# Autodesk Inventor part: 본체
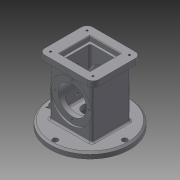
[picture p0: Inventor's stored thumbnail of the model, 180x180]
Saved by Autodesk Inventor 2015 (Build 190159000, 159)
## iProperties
Created: 2019-08
Part Number: 본체
Material: 일반
Document SubType Name: Modeling
Designer: now
Density: 1 g/cm^3
Appearance: 기본값
Author: now
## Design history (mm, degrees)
sketch "스케치1"
  geometry: C1 r 67.5 at (0, 0); 1 further point
  constraints: 1 centre point, 1 coincident
  dimensions: "d0" = 135 diameter of C1
extrude "돌출1" new body sketch "스케치1" distance "d1" = 10; taper "d2" = 0 deg
sketch "스케치2"
  geometry: L1 (-36, 33)-(36, 33); L2 (36, 33)-(36, -33); L3 (36, -33)-(-36, -33); L4 (-36, -33)-(-36, 33); L5 (-36, 33)-(36, -33); L6 (36, 33)-(-36, -33); C1 r 67.5 at (0, 0) reference
  constraints: 12 end point, 2 midpoint, 2 parallel, 1 horizontal, 1 perpendicular
  dimensions: "d3" = 72 distance of L1.start L1.end; "d4" = 66 distance of L3.end L1.start
extrude "돌출2" join sketch "스케치2" distance "d5" = 98; taper "d6" = 0 deg
sketch "스케치4"
  geometry: L1 (-31.5, -10)-(103.5, -10) reference; C1 r 35 at (36, 44); 2 further points
  constraints: 1 centre point, 1 midpoint, 1 vertical alignment
  dimensions: "d8" = 70 diameter of C1; "d9" = 54 distance from line of L1 C1.centre
extrude "돌출3" cut sketch "스케치4" distance "d10" = 3; taper "d11" = 0 deg
sketch "스케치5"
  geometry: C1 r 35 at (0, 0) reference; 1 further point
hole "구멍1" sketch "스케치5" at (0, 0) diameter "d12" = 48; stored, may be unused: countersink angle "d16" = 90 deg, drill point angle "d18" = 118 deg; dims "d13" = 6, "d14" = 4, "d15" = 2, "d17" = 8
fillet "모깎기1" dims "d19" = 3
fillet "모깎기2" dims "d20" = 3
sketch "스케치6"
  geometry: L1 (-46, 41)-(46, 41); L2 (46, 41)-(46, -41); L3 (46, -41)-(-46, -41); L4 (-46, -41)-(-46, 41); L5 (-46, 41)-(46, -41); L6 (46, 41)-(-46, -41); 1 further point
  constraints: 12 end point, 2 midpoint, 2 parallel, 1 horizontal, 1 perpendicular
  dimensions: "d21" = 82 distance of L1.end L2.end; "d22" = 92 distance of L1.start L1.end
extrude "돌출4" join sketch "스케치6" distance "d23" = 10; taper "d24" = 0 deg
fillet "모깎기3" dims "d25" = 10
node "작업 평면2"
sketch "스케치10"
  geometry: C1 r 24 at (0, 0) reference; 2 further points
  constraints: 1 vertical alignment
  dimensions: "d45" = 29 distance of C1.centre point (0, 29)
hole "구멍3" sketch "스케치10" at (0, 29) diameter "d46" = 3.242; stored, may be unused: countersink angle "d50" = 90 deg, drill point angle "d52" = 118 deg; dims "d47" = 4, "d48" = 4, "d49" = 2, "d51" = 6
chamfer "모따기2" distance "d56" = 3; stored, may be unused: second distance "d57" = 2, angle "d58" = 45 deg
sketch "스케치14"
  geometry: C1 r 67.5 at (0, 0) reference; C2 r 25 at (0, 0)
  constraints: 1 centre point, 1 coincident
  dimensions: "d74" = 50 diameter of C2
extrude "돌출9" cut sketch "스케치14" distance "d75" = 18; taper "d76" = 0 deg
fillet "모깎기5" dims "d84" = 3
sketch "스케치17" dims "d96" = 118
  geometry: C1 r 64.5 at (0, 0) reference; 2 further points
  constraints: 2 vertical alignment, 1 coincident, 2 other
hole "구멍7" sketch "스케치17" at (0, 59) diameter "d97" = 9; stored, may be unused: countersink angle "d101" = 90 deg, drill point angle "d103" = 118 deg; dims "d98" = 50, "d99" = 4, "d100" = 2, "d102" = 59.3
sketch "스케치18"
  geometry: C1 r 64.5 at (0, 0) reference; A1 r 59 centre (0, 0) between (0, -59) and (59, 0)
  constraints: 2 point on circle, 1 centre point, 1 coincident, 1 horizontal alignment, 1 vertical alignment
  dimensions: "d107" = 118 diameter of A1
hole "구멍8" sketch "스케치18" at (0, -59), (59, 0) diameter "d108" = 9; stored, may be unused: countersink angle "d112" = 90 deg, drill point angle "d114" = 118 deg; dims "d109" = 50, "d110" = 4, "d111" = 2, "d113" = 59.3
sketch "스케치19"
  geometry: C1 r 64.5 at (0, 0) reference; C2 r 59 at (0, 0)
  constraints: 1 centre point, 1 coincident, 1 other
  dimensions: "d115" = 118 diameter of C2
feature "엠보싱1" sketch "스케치19" dims "d116" = 0.5, "d117" = 0
sketch "스케치20"
  geometry: L1 (-13, 97.5)-(-13, -37.5) reference; 3 further points
  constraints: 2 horizontal alignment
  dimensions: "d132" = 37 distance from line of point (24, 30) L1; "d133" = 43 distance of point (67, 30) point (24, 30)
hole "구멍9" sketch "스케치20" at (67, 30), (24, 30) diameter "d120" = 4.917; stored, may be unused: countersink angle "d124" = 90 deg, drill point angle "d126" = 118 deg; dims "d121" = 12, "d122" = 4, "d123" = 2, "d125" = 35
sketch "스케치21"
  geometry: C1 r 22 at (0, 0) reference; C2 r 12.5 at (0, 0)
  constraints: 1 centre point, 1 coincident
  dimensions: "d129" = 25 diameter of C2
extrude "돌출10" cut sketch "스케치21" stored distance "d130" = 10; taper "d131" = 0 deg
sketch "스케치22"
  geometry: L1 (-22, -22)-(-22, 22) reference; L2 (-22, 22)-(19, 22) reference; L3 (22, 19)-(22, -22) reference; L4 (22, -22)-(-22, -22) reference; L5 (-26, -26)-(26, -26); L6 (26, -26)-(26, 26); L7 (26, 26)-(-26, 26); L8 (-26, 26)-(-26, -26); L9 (-26, -26)-(26, 26); L10 (26, -26)-(-26, 26); A1 r 3 centre (19, 19) between (22, 19) and (19, 22) reference; 1 further point
  constraints: 12 end point, 2 midpoint, 2 parallel, 1 horizontal, 1 perpendicular
  dimensions: "d134" = 52 distance of L6.end L7.end; "d135" = 52 distance between parallel lines of L5 L7
extrude "돌출11" cut sketch "스케치22" distance "d136" = 8; taper "d137" = 0 deg
node "작업 평면1"
chamfer "모따기3" distance "d152" = 1; stored, may be unused: second distance "d153" = 2, angle "d154" = 45 deg
sketch "스케치26"
  geometry: L1 (-26, -26)-(26, -26); L2 (26, -26)-(26, 26); L3 (26, 26)-(-26, 26); L4 (-26, 26)-(-26, -26); L5 (-26, -26)-(26, 26); L6 (26, -26)-(-26, 26); 1 further point
  constraints: 12 end point, 2 midpoint, 2 parallel, 1 horizontal, 1 perpendicular
  dimensions: "d155" = 52 distance of L3.end L1.start; "d156" = 52 distance between parallel lines of L4 L2
extrude "돌출13" cut sketch "스케치26" distance "d157" = 8; taper "d158" = 0 deg
sketch "스케치27"
  geometry: L1 (-22, -22)-(22, -22); L2 (22, -22)-(22, 22); L3 (22, 22)-(-22, 22); L4 (-22, 22)-(-22, -22); L5 (-22, -22)-(22, 22); L6 (22, -22)-(-22, 22); C1 r 12.5 at (0, 0) reference
  constraints: 12 end point, 2 midpoint, 2 parallel, 1 horizontal, 1 perpendicular
  dimensions: "d159" = 44 distance of L2.end L3.end; "d160" = 44 distance of L3.end L1.start
extrude "돌출14" cut sketch "스케치27" distance "d161" = 74; taper "d162" = 0 deg
fillet "모깎기11" dims "d163" = 3
fillet "모깎기12" dims "d164" = 3
fillet "모깎기13" dims "d165" = 3
sketch "스케치28"
  geometry: A1 r 10 centre (36, 31) between (46, 31) and (36, 41) reference; A2 r 10 centre (-36, 31) between (-36, 41) and (-46, 31) reference; A3 r 10 centre (-36, -31) between (-46, -31) and (-36, -41) reference; A4 r 10 centre (36, -31) between (36, -41) and (46, -31) reference; 1 further point
hole "구멍11" sketch "스케치28" at (36, -31), (-36, 31), (36, 31), (-36, -31) diameter "d166" = 3.242; stored, may be unused: countersink angle "d170" = 90 deg, drill point angle "d172" = 118 deg; dims "d167" = 4, "d168" = 4, "d169" = 2, "d171" = 6
node "솔리드1"
pattern_circular "원형 패턴1" dims angle "d54" = 360 deg
mirror "대칭1"
